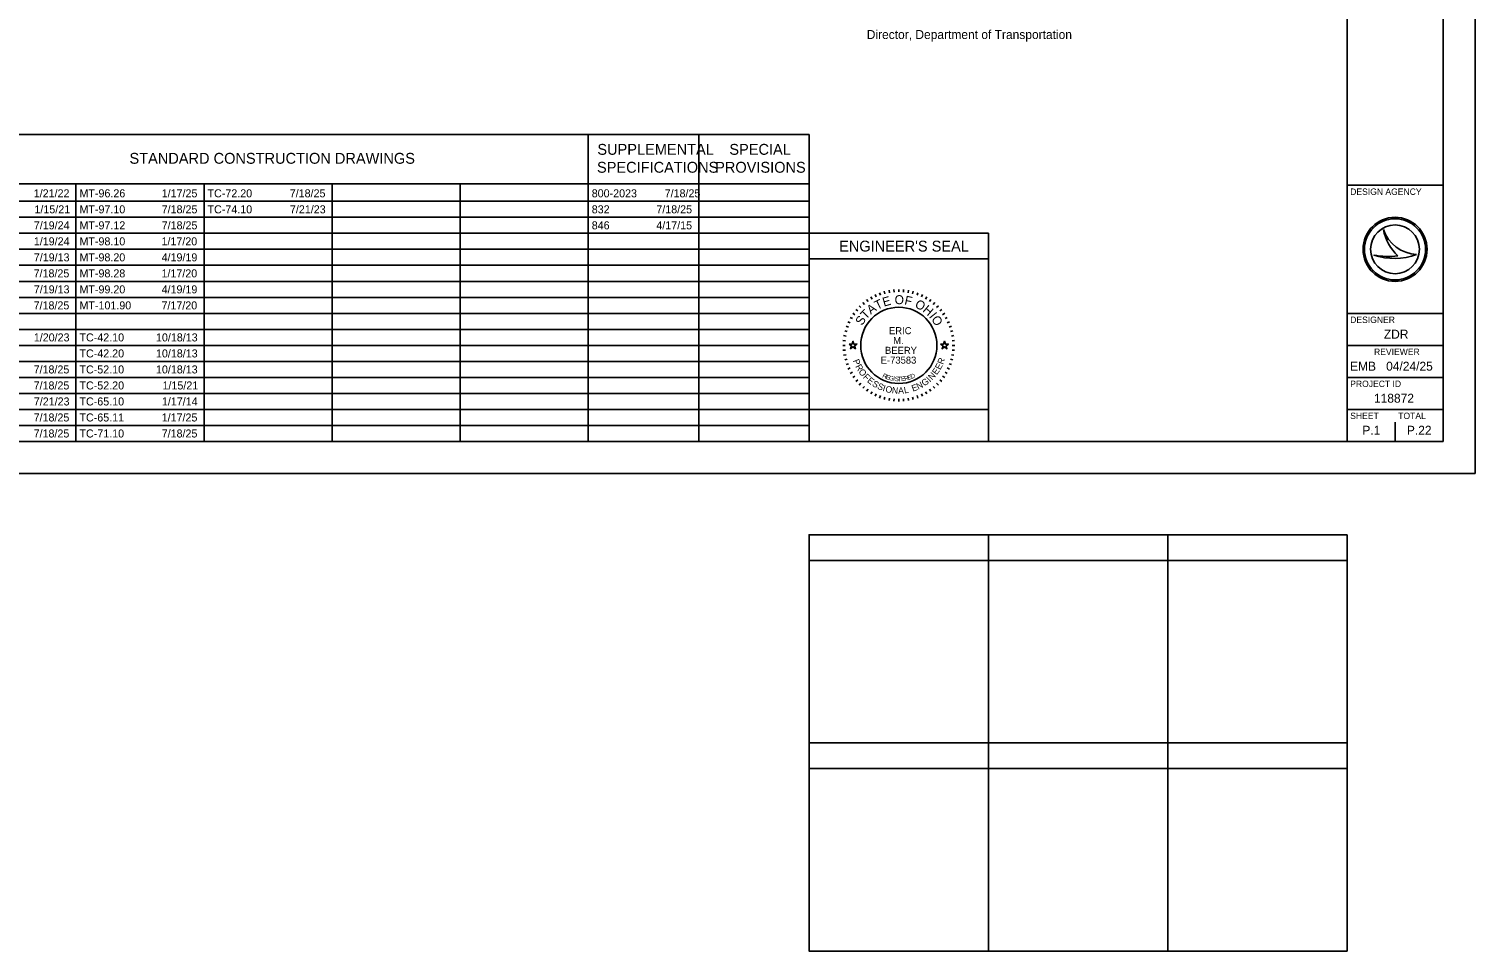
# Model space of a CAD drawing. Extents: x 0 to 34, y -7.5 to 22.
# Drawn here: x 11.42 to 34, y -7.46 to 6.94 of the extents above; entities that cross this region are included whole.
import ezdxf

# ---------------------------------------------------------------- set-up
doc = ezdxf.new("R2010")
doc.units = 0
for name, color, linetype in [('Default', 7, 'Continuous'), ('SH_Border', 7, 'Continuous'), ('SH_Cut_Line', 7, 'Continuous'), ('SH_Data', 7, 'Continuous'), ('SH_Seal', 7, 'Continuous'), ('SH_Text', 7, 'Continuous')]:
    doc.layers.add(name, color=color, linetype=linetype)

msp = doc.modelspace()

# ---------------------------------------------------------------- linework, layer by layer
at = {"layer": 'SH_Border'}
for p, q in [((32, 0.5), (32, 21.5)), ((32, 4.5), (33.5, 4.5)), ((32, 2.5), (33.5, 2.5)), ((32, 2), (33.5, 2)), ((32, 1.5), (33.5, 1.5)), ((32, 1), (33.5, 1))]:
    msp.add_line(p, q, dxfattribs=at)
msp.add_lwpolyline([(1.5, 21.5), (33.5, 21.5), (33.5, 0.5), (1.5, 0.5)], close=True, dxfattribs=at)
at = {"layer": 'SH_Cut_Line'}
msp.add_lwpolyline([(0, 0), (34, 0), (34, 22), (0, 22)], close=True, dxfattribs=at)
at = {"layer": 'SH_Data'}
for p, q in [((10.15, 5.292), (23.6, 5.292)), ((20.15, 0.5), (20.15, 5.292)), ((21.875, 0.5), (21.875, 5.292)), ((23.6, 0.5), (23.6, 5.292)), ((10.15, 4.521), (23.6, 4.521)), ((12.15, 0.5), (12.15, 4.521)), ((14.15, 0.5), (14.15, 4.521)), ((16.15, 0.5), (16.15, 4.521)), ((18.15, 0.5), (18.15, 4.521)), ((10.15, 4.25), (23.6, 4.25)), ((10.15, 4), (23.6, 4)), ((10.15, 3.75), (23.6, 3.75)), ((23.6, 0.5), (23.6, 3.75)), ((23.6, 3.75), (26.4, 3.75)), ((26.4, 3.75), (26.4, 0.5)), ((32.567, 3.81), (32.567, 3.81)), ((10.15, 3.5), (23.6, 3.5)), ((32.417, 3.41), (32.417, 3.41)), ((32.75, 3.5), (32.75, 3.5)), ((33.087, 3.419), (33.087, 3.419)), ((10.15, 3.25), (23.6, 3.25)), ((23.6, 3.35), (26.4, 3.35)), ((10.15, 3), (23.6, 3)), ((10.15, 2.75), (23.6, 2.75)), ((10.15, 2.5), (23.6, 2.5)), ((10.15, 2.25), (23.6, 2.25)), ((10.15, 2), (23.6, 2)), ((10.15, 1.75), (23.6, 1.75)), ((10.15, 1.5), (23.6, 1.5)), ((10.15, 1.25), (23.6, 1.25)), ((10.15, 1), (23.6, 1)), ((10.15, 0.75), (23.6, 0.75)), ((32.75, 0.5), (32.75, 0.8)), ((23.6, 0.5), (26.4, 0.5)), ((32.375, 0.675), (32.375, 0.675)), ((23.6, -1.357), (26.4, -1.357)), ((26.4, -1.357), (29.2, -1.357)), ((29.2, -1.357), (32, -1.357)), ((23.6, -4.607), (26.4, -4.607)), ((26.4, -4.607), (29.2, -4.607)), ((29.2, -4.607), (32, -4.607))]:
    msp.add_line(p, q, dxfattribs=at)
for points in [[(23.6, 0.5), (23.6, 1), (26.4, 1), (26.4, 0.5)], [(26.4, -0.957), (23.6, -0.957), (23.6, -4.207), (26.4, -4.207)], [(29.2, -0.957), (26.4, -0.957), (26.4, -4.207), (29.2, -4.207)], [(32, -0.957), (29.2, -0.957), (29.2, -4.207), (32, -4.207)], [(26.4, -4.207), (23.6, -4.207), (23.6, -7.457), (26.4, -7.457)], [(29.2, -4.207), (26.4, -4.207), (26.4, -7.457), (29.2, -7.457)], [(32, -4.207), (29.2, -4.207), (29.2, -7.457), (32, -7.457)]]:
    msp.add_lwpolyline(points, close=True, dxfattribs=at)
for radius in [0.5, 0.477, 0.477, 0.382]:
    msp.add_circle((32.75, 3.5), radius, dxfattribs=at)
for centre, radius, start, end in [((33.116, 3.998), 0.58, 198.9257, 198.9319), ((33.347, 3.97), 0.796, 191.6379, 191.6421), ((33.116, 3.998), 0.58, 198.9319, 267.1657), ((33.347, 3.97), 0.796, 191.6421, 226.0947), ((32.739, 4.37), 1.013, 251.4576, 290.0832), ((32.648, 4.654), 1.266, 259.4964, 259.4995), ((32.739, 4.37), 1.013, 251.4527, 251.4576), ((32.648, 4.654), 1.266, 259.4995, 276.6672)]:
    msp.add_arc(centre, radius, start, end, dxfattribs=at)
at = {"layer": 'SH_Seal'}
for p, q in [((24.498, 2.717), (24.521, 2.684)), ((24.563, 2.758), (24.583, 2.723)), ((24.63, 2.793), (24.647, 2.757)), ((24.701, 2.822), (24.714, 2.785)), ((24.774, 2.845), (24.784, 2.807)), ((24.848, 2.862), (24.855, 2.822)), ((24.924, 2.872), (24.927, 2.832)), ((25, 2.875), (25, 2.835)), ((25.076, 2.872), (25.073, 2.832)), ((25.152, 2.862), (25.145, 2.822)), ((25.226, 2.845), (25.216, 2.807)), ((25.299, 2.822), (25.286, 2.785)), ((25.37, 2.793), (25.353, 2.757)), ((25.437, 2.758), (25.417, 2.723)), ((25.502, 2.717), (25.479, 2.684)), ((24.283, 2.502), (24.316, 2.479)), ((24.33, 2.562), (24.36, 2.537)), ((24.381, 2.619), (24.41, 2.59)), ((24.438, 2.67), (24.463, 2.64)), ((25.562, 2.67), (25.537, 2.64)), ((25.619, 2.619), (25.59, 2.59)), ((25.67, 2.562), (25.64, 2.537)), ((25.717, 2.502), (25.684, 2.479)), ((24.178, 2.299), (24.215, 2.286)), ((24.207, 2.37), (24.243, 2.353)), ((24.242, 2.438), (24.277, 2.418)), ((25.758, 2.438), (25.723, 2.418)), ((25.793, 2.37), (25.757, 2.353)), ((25.822, 2.299), (25.785, 2.286)), ((24.128, 2.076), (24.168, 2.073)), ((24.138, 2.152), (24.178, 2.145)), ((24.155, 2.226), (24.193, 2.216)), ((25.845, 2.226), (25.807, 2.216)), ((25.862, 2.152), (25.822, 2.145)), ((25.872, 2.076), (25.832, 2.073)), ((24.125, 2), (24.165, 2)), ((24.128, 1.924), (24.168, 1.927)), ((24.138, 1.848), (24.178, 1.855)), ((25.862, 1.848), (25.822, 1.855)), ((25.872, 1.924), (25.832, 1.927)), ((25.875, 2), (25.835, 2)), ((24.155, 1.774), (24.193, 1.784)), ((24.178, 1.701), (24.215, 1.714)), ((24.207, 1.63), (24.243, 1.647)), ((24.242, 1.562), (24.277, 1.583)), ((25.758, 1.562), (25.723, 1.583)), ((25.793, 1.63), (25.757, 1.647)), ((25.822, 1.701), (25.785, 1.714)), ((25.845, 1.774), (25.807, 1.784)), ((24.283, 1.498), (24.316, 1.521)), ((24.33, 1.438), (24.36, 1.463)), ((24.381, 1.381), (24.41, 1.41)), ((24.438, 1.33), (24.463, 1.36)), ((25.562, 1.33), (25.537, 1.36)), ((25.619, 1.381), (25.59, 1.41)), ((25.67, 1.438), (25.64, 1.463)), ((25.717, 1.498), (25.684, 1.521)), ((24.498, 1.283), (24.521, 1.316)), ((24.563, 1.242), (24.583, 1.277)), ((24.63, 1.207), (24.647, 1.243)), ((24.701, 1.178), (24.714, 1.215)), ((24.774, 1.155), (24.784, 1.193)), ((24.848, 1.138), (24.855, 1.178)), ((24.924, 1.128), (24.927, 1.168)), ((25, 1.125), (25, 1.165)), ((25.076, 1.128), (25.073, 1.168)), ((25.152, 1.138), (25.145, 1.178)), ((25.226, 1.155), (25.216, 1.193)), ((25.299, 1.178), (25.286, 1.215)), ((25.37, 1.207), (25.353, 1.243)), ((25.437, 1.242), (25.417, 1.277)), ((25.502, 1.283), (25.479, 1.316))]:
    msp.add_line(p, q, dxfattribs=at)
for points in [[(24.224, 2.02), (24.271, 2.02), (24.285, 2.065), (24.299, 2.02), (24.346, 2.02), (24.308, 1.992), (24.323, 1.948), (24.285, 1.975), (24.247, 1.948), (24.262, 1.992)], [(25.654, 2.02), (25.701, 2.02), (25.715, 2.065), (25.729, 2.02), (25.776, 2.02), (25.738, 1.992), (25.753, 1.948), (25.715, 1.975), (25.677, 1.948), (25.692, 1.992)]]:
    msp.add_lwpolyline(points, close=True, dxfattribs=at)
msp.add_circle((25, 2), 0.595, dxfattribs=at)

# ---------------------------------------------------------------- texts
at = {"layer": 'Default'}
for s, p in [('1/21/22', (11.491, 4.312)), ('MT-96.26', (12.205, 4.312)), ('1/17/25', (13.489, 4.312)), ('TC-72.20', (14.205, 4.312)), ('7/18/25', (15.489, 4.312)), ('800-2023', (20.205, 4.312)), ('7/18/25', (21.344, 4.312)), ('1/15/21', (11.502, 4.062)), ('MT-97.10', (12.205, 4.062)), ('7/18/25', (13.489, 4.062)), ('TC-74.10', (14.205, 4.062)), ('7/21/23', (15.492, 4.062)), ('832', (20.205, 4.062)), ('7/18/25', (21.214, 4.062)), ('7/19/24', (11.492, 3.812)), ('MT-97.12', (12.205, 3.812)), ('7/18/25', (13.489, 3.812)), ('846', (20.205, 3.812)), ('4/17/15', (21.214, 3.812)), ('1/19/24', (11.492, 3.562)), ('MT-98.10', (12.205, 3.562)), ('1/17/20', (13.486, 3.562)), ('7/19/13', (11.492, 3.312)), ('MT-98.20', (12.205, 3.312)), ('4/19/19', (13.488, 3.312)), ('7/18/25', (11.489, 3.062)), ('MT-98.28', (12.205, 3.062)), ('1/17/20', (13.486, 3.062)), ('7/19/13', (11.492, 2.812)), ('MT-99.20', (12.205, 2.812)), ('4/19/19', (13.488, 2.812)), ('7/18/25', (11.489, 2.562)), ('MT-101.90', (12.205, 2.562)), ('7/17/20', (13.486, 2.562)), ('1/20/23', (11.492, 2.062)), ('TC-42.10', (12.205, 2.062)), ('10/18/13', (13.4, 2.062)), ('TC-42.20', (12.205, 1.812)), ('10/18/13', (13.4, 1.812)), ('7/18/25', (11.489, 1.562)), ('TC-52.10', (12.205, 1.562)), ('10/18/13', (13.4, 1.562)), ('7/18/25', (11.489, 1.312)), ('TC-52.20', (12.205, 1.312)), ('1/15/21', (13.502, 1.312)), ('7/21/23', (11.492, 1.062)), ('TC-65.10', (12.205, 1.062)), ('1/17/14', (13.492, 1.062)), ('7/18/25', (11.489, 0.812)), ('TC-65.11', (12.205, 0.812)), ('1/17/25', (13.489, 0.812)), ('7/18/25', (11.489, 0.562)), ('TC-71.10', (12.205, 0.562)), ('7/18/25', (13.489, 0.562))]:
    msp.add_text(s, height=0.125, dxfattribs=at).set_placement(p)
at = {"layer": 'SH_Data'}
for s, height, p in [('DESIGN AGENCY', 0.1, (32.05, 4.35)), ("ENGINEER'S SEAL", 0.17, (24.068, 3.465)), ('DESIGNER', 0.1, (32.05, 2.35)), ('ZDR', 0.14, (32.575, 2.105)), ('REVIEWER', 0.1, (32.422, 1.85)), ('EMB', 0.14, (32.047, 1.605)), ('04/24/25', 0.14, (32.611, 1.605)), ('PROJECT ID', 0.1, (32.05, 1.35)), ('118872', 0.14, (32.421, 1.105)), ('SHEET', 0.1, (32.05, 0.85)), ('TOTAL', 0.1, (32.8, 0.85)), ('P.1', 0.14, (32.24, 0.605)), ('P.22', 0.14, (32.935, 0.605))]:
    msp.add_text(s, height=height, dxfattribs=at).set_placement(p)
at = {"layer": 'SH_Seal'}
for s, height, rotation, p in [('T', 0.14, 25.7167, (24.662, 2.552)), ('E', 0.14, 15.7571, (24.768, 2.604)), ('O', 0.14, 359.7812, (24.935, 2.644)), ('F', 0.14, 347.4362, (25.081, 2.642)), ('T', 0.14, 46.4344, (24.488, 2.396)), ('A', 0.14, 36.4747, (24.563, 2.478)), ('O', 0.14, 332.2586, (25.24, 2.602)), ('H', 0.14, 319.9136, (25.363, 2.536)), ('I', 0.14, 308.367, (25.466, 2.448)), ('S', 0.14, 57.1924, (24.428, 2.301)), ('O', 0.14, 303.1491, (25.502, 2.409)), ('P', 0.1, 291.494, (24.282, 1.762)), ('R', 0.1, 298.7311, (24.319, 1.672)), ('O', 0.1, 306.4666, (24.365, 1.588)), ('N', 0.1, 47.0224, (25.52, 1.451)), ('E', 0.1, 54.758, (25.593, 1.531)), ('E', 0.1, 61.9951, (25.648, 1.61)), ('R', 0.1, 69.2322, (25.692, 1.695)), ('F', 0.1, 314.7068, (24.434, 1.498)), ('E', 0.1, 321.4393, (24.498, 1.435)), ('S', 0.1, 328.6764, (24.574, 1.375)), ('S', 0.1, 335.9134, (24.656, 1.327)), ('R', 0.07, 334.487, (24.737, 1.505)), ('I', 0.1, 343.1505, (24.741, 1.29)), ('E', 0.07, 341.04, (24.791, 1.48)), ('O', 0.1, 346.8859, (24.784, 1.275)), ('G', 0.07, 347.4752, (24.841, 1.462)), ('I', 0.07, 353.7858, (24.909, 1.447)), ('S', 0.07, 356.8926, (24.936, 1.443)), ('T', 0.07, 3.0061, (24.986, 1.439)), ('E', 0.07, 6.0117, (25.039, 1.441)), ('R', 0.07, 11.9184, (25.092, 1.447)), ('E', 0.07, 17.6836, (25.15, 1.46)), ('D', 0.07, 23.3052, (25.201, 1.477)), ('E', 0.1, 20.0742, (25.221, 1.277)), ('N', 0.1, 27.3113, (25.304, 1.308)), ('G', 0.1, 35.0469, (25.398, 1.357)), ('I', 0.1, 43.287, (25.487, 1.421)), ('N', 0.1, 355.1261, (24.889, 1.252)), ('A', 0.1, 2.8617, (24.992, 1.244)), ('L', 0.1, 10.0987, (25.089, 1.249))]:
    msp.add_text(s, height=height, rotation=rotation, dxfattribs=at).set_placement(p)
for s, p in [('ERIC', (24.847, 2.175)), ('M.', (24.913, 2.022)), ('E-73583', (24.718, 1.715)), ('BEERY', (24.785, 1.868))]:
    msp.add_text(s, height=0.11, dxfattribs=at).set_placement(p)
at = {"layer": 'SH_Text'}
for s, height, p in [('Director, Department of Transportation', 0.14, (24.5, 6.784)), ('STANDARD CONSTRUCTION DRAWINGS', 0.17, (12.986, 4.836)), ('SUPPLEMENTAL', 0.17, (20.293, 4.976)), ('SPECIAL', 0.17, (22.354, 4.976)), ('SPECIFICATIONS', 0.17, (20.287, 4.696)), ('PROVISIONS', 0.17, (22.132, 4.696))]:
    msp.add_text(s, height=height, dxfattribs=at).set_placement(p)

doc.saveas('drawing.dxf')
